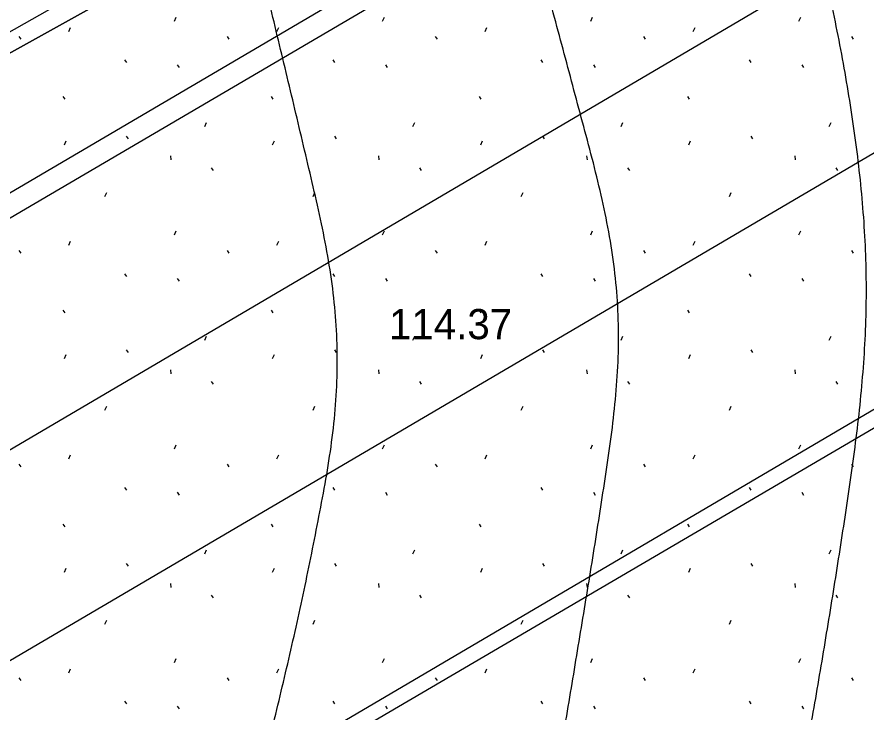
# Model space of a CAD drawing. Extents: x 412225 to 413380, y 4456471 to 4457189.
# Drawn here: x 413112.58 to 413146.44, y 4456831.09 to 4456858.79 of the extents above; entities that cross this region are included whole.
import ezdxf

# ---------------------------------------------------------------- set-up
doc = ezdxf.new("R2010")
doc.units = 0
for name, color, linetype in [('0_HALİHAZIR', 7, 'Continuous'), ('0_KADASTRO', 7, 'Continuous'), ('Level 41', 7, 'Continuous'), ('Level 54', 7, 'Continuous')]:
    doc.layers.add(name, color=color, linetype=linetype)

msp = doc.modelspace()

# ---------------------------------------------------------------- linework, layer by layer
at = {"layer": '0_HALİHAZIR'}
for points in [[(413308.103, 4456965.941), (413265.175, 4456940.384), (413047.239, 4456812.664), (412821.475, 4456681.363)], [(412841.576, 4456665.003), (413057.926, 4456790.466), (413273.464, 4456916.652), (413307.769, 4456936.91)], [(413101.589, 4456792.443), (413098.903, 4456797.22), (413080.986, 4456840.51), (413124.68, 4456865.219), (413175.605, 4456894.045), (413228.652, 4456922.382), (413248.055, 4456932.336), (413262.23, 4456891.913), (413262.792, 4456889.108), (413224.6, 4456867.435), (413186.768, 4456846.773), (413140.241, 4456816.307), (413141.746, 4456812.452)]]:
    msp.add_lwpolyline(points, dxfattribs=at)
for points in [[(413185.041, 4456825.516), (413184.865, 4456828.511), (413184.709, 4456831.506), (413184.582, 4456834.504), (413184.566, 4456837.501), (413184.755, 4456840.482), (413185.195, 4456843.441), (413185.816, 4456846.375), (413186.471, 4456849.302), (413187.02, 4456852.247), (413187.379, 4456855.217), (413187.478, 4456858.207), (413187.289, 4456861.187), (413186.83, 4456864.143), (413186.153, 4456867.062), (413185.337, 4456869.947), (413184.414, 4456872.8), (413183.4, 4456875.622), (413182.157, 4456878.336), (413180.573, 4456880.826), (413178.63, 4456883.087), (413176.485, 4456885.183), (413174.317, 4456887.257), (413172.212, 4456889.39), (413170.207, 4456891.616), (413168.296, 4456893.927), (413166.447, 4456896.289), (413164.633, 4456898.679), (413162.836, 4456901.081), (413161.013, 4456903.463), (413159.114, 4456905.781), (413157.112, 4456908.012), (413155.014, 4456910.154), (413152.817, 4456912.193), (413150.5, 4456914.086), (413148.049, 4456915.802), (413145.487, 4456917.358), (413142.861, 4456918.806), (413140.095, 4456919.757), (413137.24, 4456920.427), (413134.82, 4456921.48), (413134.285, 4456921.968)], [(413176.077, 4456827.781), (413176.22, 4456830.778), (413176.362, 4456833.775), (413176.504, 4456836.771), (413176.66, 4456839.767), (413176.833, 4456842.762), (413177.017, 4456845.756), (413177.167, 4456848.752), (413177.234, 4456851.75), (413177.176, 4456854.746), (413176.983, 4456857.738), (413176.658, 4456860.718), (413176.198, 4456863.68), (413175.553, 4456866.603), (413174.664, 4456869.456), (413173.469, 4456872.19), (413172, 4456874.791), (413170.353, 4456877.296), (413168.638, 4456879.757), (413166.915, 4456882.214), (413165.189, 4456884.667), (413163.46, 4456887.119), (413161.731, 4456889.57), (413160.001, 4456892.022), (413158.269, 4456894.471), (413156.53, 4456896.916), (413154.769, 4456899.344), (413152.97, 4456901.744), (413151.114, 4456904.1), (413149.196, 4456906.406), (413147.216, 4456908.659), (413145.17, 4456910.851), (413142.932, 4456912.817), (413140.47, 4456914.442), (413137.714, 4456915.514), (413134.845, 4456915.944), (413131.864, 4456916.014), (413129.101, 4456916.531), (413127.846, 4456917.947), (413127.82, 4456918.044)], [(413165.333, 4456820.404), (413165.763, 4456823.374), (413166.194, 4456826.342), (413166.626, 4456829.311), (413167.058, 4456832.28), (413167.457, 4456835.253), (413167.773, 4456838.234), (413167.922, 4456841.224), (413167.918, 4456844.221), (413167.789, 4456847.218), (413167.6, 4456850.211), (413167.353, 4456853.201), (413167.043, 4456856.184), (413166.668, 4456859.16), (413166.227, 4456862.127), (413165.713, 4456865.082), (413164.969, 4456867.974), (413163.873, 4456870.717), (413162.447, 4456873.344), (413160.86, 4456875.89), (413159.279, 4456878.439), (413157.699, 4456880.99), (413156.119, 4456883.54), (413154.538, 4456886.09), (413152.953, 4456888.637), (413151.333, 4456891.161), (413149.669, 4456893.656), (413147.947, 4456896.112), (413146.188, 4456898.542), (413144.392, 4456900.945), (413142.555, 4456903.316), (413140.673, 4456905.652), (413138.718, 4456907.925), (413136.505, 4456909.877), (413133.978, 4456911.273), (413131.134, 4456912.117), (413128.188, 4456912.678), (413125.238, 4456913.221), (413125.086, 4456913.253)], [(413152.977, 4456814.674), (413153.414, 4456817.641), (413153.905, 4456820.599), (413154.456, 4456823.548), (413155.022, 4456826.494), (413155.559, 4456829.446), (413156.035, 4456832.407), (413156.435, 4456835.379), (413156.76, 4456838.361), (413157.003, 4456841.35), (413157.144, 4456844.345), (413157.165, 4456847.343), (413157.059, 4456850.339), (413156.836, 4456853.329), (413156.505, 4456856.309), (413156.076, 4456859.277), (413155.559, 4456862.231), (413154.914, 4456865.158), (413154.049, 4456868.018), (413152.935, 4456870.789), (413151.62, 4456873.483), (413150.217, 4456876.134), (413148.775, 4456878.765), (413147.298, 4456881.376), (413145.787, 4456883.968), (413144.243, 4456886.54), (413142.653, 4456889.083), (413140.996, 4456891.582), (413139.263, 4456894.029), (413137.448, 4456896.417), (413135.549, 4456898.737), (413133.542, 4456900.962), (413131.409, 4456903.064), (413129.452, 4456904.831)], [(413141.718, 4456801.674), (413141.533, 4456804.668), (413141.345, 4456807.662), (413141.141, 4456810.655), (413141.173, 4456813.636), (413141.462, 4456816.58), (413142.039, 4456819.523), (413142.654, 4456822.459), (413143.242, 4456825.401), (413143.801, 4456828.349), (413144.332, 4456831.301), (413144.834, 4456834.259), (413145.31, 4456837.221), (413145.761, 4456840.187), (413146.143, 4456843.161), (413146.377, 4456846.145), (413146.398, 4456849.137), (413146.195, 4456852.125), (413145.812, 4456855.097), (413145.291, 4456858.05), (413144.659, 4456860.981), (413143.926, 4456863.889), (413143.086, 4456866.767), (413142.132, 4456869.609), (413141.061, 4456872.409), (413139.878, 4456875.164), (413138.596, 4456877.875), (413137.23, 4456880.545), (413135.801, 4456883.182), (413134.325, 4456885.794), (413132.81, 4456888.383), (413131.247, 4456890.943), (413129.626, 4456893.466), (413127.928, 4456895.938), (413126.108, 4456898.317), (413124.166, 4456900.595), (413123.465, 4456901.336)], [(413132.18, 4456801.915), (413131.534, 4456804.844), (413131.015, 4456807.794), (413130.788, 4456810.765), (413130.972, 4456813.727), (413131.528, 4456816.661), (413132.242, 4456819.574), (413132.925, 4456822.49), (413133.509, 4456825.432), (413134.034, 4456828.386), (413134.538, 4456831.343), (413135.031, 4456834.302), (413135.516, 4456837.263), (413135.979, 4456840.227), (413136.381, 4456843.199), (413136.542, 4456846.179), (413136.33, 4456849.135), (413135.763, 4456852.07), (413135.01, 4456854.974), (413134.234, 4456857.872), (413133.454, 4456860.768), (413132.672, 4456863.665), (413131.89, 4456866.561), (413131.111, 4456869.458), (413130.337, 4456872.356), (413129.44, 4456875.214), (413128.343, 4456877.967), (413127.02, 4456880.656), (413125.588, 4456883.292), (413124.135, 4456885.916), (413122.651, 4456888.523), (413121.13, 4456891.109), (413119.961, 4456893.047)], [(413121.034, 4456792.186), (413120.425, 4456795.121), (413119.728, 4456798.036), (413118.947, 4456800.933), (413118.191, 4456803.835), (413117.589, 4456806.767), (413117.389, 4456809.721), (413117.67, 4456812.66), (413118.378, 4456815.565), (413119.27, 4456818.429), (413120.188, 4456821.285), (413121.061, 4456824.154), (413121.868, 4456827.042), (413122.614, 4456829.948), (413123.318, 4456832.864), (413123.974, 4456835.791), (413124.571, 4456838.731), (413125.086, 4456841.685), (413125.333, 4456844.657), (413125.198, 4456847.612), (413124.705, 4456850.563), (413124.034, 4456853.487), (413123.342, 4456856.406), (413122.638, 4456859.322), (413121.932, 4456862.238), (413121.232, 4456865.155), (413120.548, 4456868.076), (413119.887, 4456871.002), (413119.247, 4456873.933), (413118.624, 4456876.868), (413118.012, 4456879.804), (413117.439, 4456882.749), (413116.97, 4456885.707), (413116.178, 4456888.543), (413115.645, 4456889.697)]]:
    msp.add_spline(points, degree=3, dxfattribs=at)
at = {"layer": '0_KADASTRO'}
msp.add_lwpolyline([(413081.18, 4456863.89), (413117.11, 4456885.191), (413114.748, 4456889.381), (413112.325, 4456893.68), (413114.95, 4456895.426), (413121.901, 4456899.897), (413122.52, 4456900.295), (413129.339, 4456904.681), (413130.089, 4456905.163), (413137.659, 4456910.032), (413145.228, 4456914.9), (413152.798, 4456919.769), (413160.405, 4456924.498), (413163.636, 4456926.04), (413168.332, 4456928.282), (413168.13, 4456928.684), (413171.177, 4456930.172), (413172.785, 4456930.957), (413174.23, 4456928.127), (413188.699, 4456899.781), (413084.666, 4456842.03), (413081.416, 4456862.441)], close=True, dxfattribs=at)
msp.add_lwpolyline([(413101.802, 4456789.154), (413081.926, 4456838.759), (413084.666, 4456842.03), (413188.699, 4456899.781), (413227.203, 4456920.401), (413243.637, 4456929.202), (413244.91, 4456926.572), (413267.668, 4456885.105), (413263.645, 4456882.832), (413242.448, 4456870.545), (413228.112, 4456862.238), (413213.766, 4456853.922), (413193.383, 4456842.116), (413184.691, 4456837.083), (413183.689, 4456836.502), (413165.406, 4456825.906)], dxfattribs=at)
at = {"layer": 'Level 41'}
for p, q in [((413118.851, 4456858.628), (413118.921, 4456858.788)), ((413127.144, 4456858.628), (413127.214, 4456858.788)), ((413135.437, 4456858.628), (413135.507, 4456858.788)), ((413143.73, 4456858.628), (413143.8, 4456858.788)), ((413114.641, 4456858.22), (413114.712, 4456858.38)), ((413122.934, 4456858.22), (413123.005, 4456858.38)), ((413131.227, 4456858.22), (413131.298, 4456858.38)), ((413139.52, 4456858.22), (413139.591, 4456858.38)), ((413112.653, 4456858.012), (413112.724, 4456857.906)), ((413120.946, 4456858.012), (413121.017, 4456857.906)), ((413129.239, 4456858.012), (413129.31, 4456857.906)), ((413137.532, 4456858.012), (413137.603, 4456857.906)), ((413145.825, 4456858.012), (413145.896, 4456857.906)), ((413116.861, 4456857.083), (413116.932, 4456856.976)), ((413125.154, 4456857.083), (413125.225, 4456856.976)), ((413133.447, 4456857.083), (413133.518, 4456856.976)), ((413141.74, 4456857.083), (413141.811, 4456856.976)), ((413118.96, 4456856.891), (413119.031, 4456856.784)), ((413127.253, 4456856.891), (413127.324, 4456856.784)), ((413135.546, 4456856.891), (413135.617, 4456856.784)), ((413143.839, 4456856.891), (413143.91, 4456856.784)), ((413114.405, 4456855.63), (413114.476, 4456855.523)), ((413122.698, 4456855.63), (413122.769, 4456855.523)), ((413130.991, 4456855.63), (413131.062, 4456855.523)), ((413139.284, 4456855.63), (413139.355, 4456855.523)), ((413120.057, 4456854.437), (413120.128, 4456854.596)), ((413128.35, 4456854.437), (413128.421, 4456854.596)), ((413136.643, 4456854.437), (413136.714, 4456854.596)), ((413144.936, 4456854.437), (413145.007, 4456854.596)), ((413114.463, 4456853.708), (413114.535, 4456853.868)), ((413116.928, 4456854.053), (413116.999, 4456853.946)), ((413122.756, 4456853.708), (413122.828, 4456853.868)), ((413125.221, 4456854.053), (413125.292, 4456853.946)), ((413131.049, 4456853.708), (413131.121, 4456853.868)), ((413133.514, 4456854.053), (413133.585, 4456853.946)), ((413139.342, 4456853.708), (413139.414, 4456853.868)), ((413141.807, 4456854.053), (413141.878, 4456853.946)), ((413118.686, 4456853.262), (413118.704, 4456853.102)), ((413126.979, 4456853.262), (413126.997, 4456853.102)), ((413135.272, 4456853.262), (413135.29, 4456853.102)), ((413143.565, 4456853.262), (413143.583, 4456853.102)), ((413120.316, 4456852.792), (413120.386, 4456852.685)), ((413128.609, 4456852.792), (413128.679, 4456852.685)), ((413136.902, 4456852.792), (413136.972, 4456852.685)), ((413145.195, 4456852.792), (413145.265, 4456852.685)), ((413116.079, 4456851.648), (413116.151, 4456851.808)), ((413124.372, 4456851.648), (413124.444, 4456851.808)), ((413132.665, 4456851.648), (413132.737, 4456851.808)), ((413140.958, 4456851.648), (413141.03, 4456851.808)), ((413118.851, 4456850.118), (413118.921, 4456850.278)), ((413127.144, 4456850.118), (413127.214, 4456850.278)), ((413135.437, 4456850.118), (413135.507, 4456850.278)), ((413143.73, 4456850.118), (413143.8, 4456850.278)), ((413114.641, 4456849.71), (413114.712, 4456849.87)), ((413122.934, 4456849.71), (413123.005, 4456849.87)), ((413131.227, 4456849.71), (413131.298, 4456849.87)), ((413139.52, 4456849.71), (413139.591, 4456849.87)), ((413112.653, 4456849.502), (413112.724, 4456849.396)), ((413120.946, 4456849.502), (413121.017, 4456849.396)), ((413129.239, 4456849.502), (413129.31, 4456849.396)), ((413137.532, 4456849.502), (413137.603, 4456849.396)), ((413145.825, 4456849.502), (413145.896, 4456849.396)), ((413116.861, 4456848.573), (413116.932, 4456848.466)), ((413125.154, 4456848.573), (413125.225, 4456848.466)), ((413133.447, 4456848.573), (413133.518, 4456848.466)), ((413141.74, 4456848.573), (413141.811, 4456848.466)), ((413118.96, 4456848.381), (413119.031, 4456848.274)), ((413127.253, 4456848.381), (413127.324, 4456848.274)), ((413135.546, 4456848.381), (413135.617, 4456848.274)), ((413143.839, 4456848.381), (413143.91, 4456848.274)), ((413114.405, 4456847.12), (413114.476, 4456847.013)), ((413122.698, 4456847.12), (413122.769, 4456847.013)), ((413130.991, 4456847.12), (413131.062, 4456847.013)), ((413139.284, 4456847.12), (413139.355, 4456847.013)), ((413120.057, 4456845.927), (413120.128, 4456846.086)), ((413128.35, 4456845.927), (413128.421, 4456846.086)), ((413136.643, 4456845.927), (413136.714, 4456846.086)), ((413144.936, 4456845.927), (413145.007, 4456846.086)), ((413116.928, 4456845.543), (413116.999, 4456845.436)), ((413125.221, 4456845.543), (413125.292, 4456845.436)), ((413133.514, 4456845.543), (413133.585, 4456845.436)), ((413141.807, 4456845.543), (413141.878, 4456845.436)), ((413114.463, 4456845.198), (413114.535, 4456845.358)), ((413122.756, 4456845.198), (413122.828, 4456845.358)), ((413131.049, 4456845.198), (413131.121, 4456845.358)), ((413139.342, 4456845.198), (413139.414, 4456845.358)), ((413118.686, 4456844.752), (413118.704, 4456844.592)), ((413126.979, 4456844.752), (413126.997, 4456844.592)), ((413135.272, 4456844.752), (413135.29, 4456844.592)), ((413143.565, 4456844.752), (413143.583, 4456844.592)), ((413120.316, 4456844.282), (413120.386, 4456844.175)), ((413128.609, 4456844.282), (413128.679, 4456844.175)), ((413136.902, 4456844.282), (413136.972, 4456844.175)), ((413145.195, 4456844.282), (413145.265, 4456844.175)), ((413116.079, 4456843.138), (413116.151, 4456843.298)), ((413124.372, 4456843.138), (413124.444, 4456843.298)), ((413132.665, 4456843.138), (413132.737, 4456843.298)), ((413140.958, 4456843.138), (413141.03, 4456843.298)), ((413118.851, 4456841.608), (413118.921, 4456841.768)), ((413127.144, 4456841.608), (413127.214, 4456841.768)), ((413135.437, 4456841.608), (413135.507, 4456841.768)), ((413143.73, 4456841.608), (413143.8, 4456841.768)), ((413114.641, 4456841.2), (413114.712, 4456841.36)), ((413122.934, 4456841.2), (413123.005, 4456841.36)), ((413131.227, 4456841.2), (413131.298, 4456841.36)), ((413139.52, 4456841.2), (413139.591, 4456841.36)), ((413112.653, 4456840.992), (413112.724, 4456840.886)), ((413120.946, 4456840.992), (413121.017, 4456840.886)), ((413129.239, 4456840.992), (413129.31, 4456840.886)), ((413137.532, 4456840.992), (413137.603, 4456840.886)), ((413145.825, 4456840.992), (413145.896, 4456840.886)), ((413116.861, 4456840.063), (413116.932, 4456839.956)), ((413125.154, 4456840.063), (413125.225, 4456839.956)), ((413133.447, 4456840.063), (413133.518, 4456839.956)), ((413141.74, 4456840.063), (413141.811, 4456839.956)), ((413118.96, 4456839.871), (413119.031, 4456839.764)), ((413127.253, 4456839.871), (413127.324, 4456839.764)), ((413135.546, 4456839.871), (413135.617, 4456839.764)), ((413143.839, 4456839.871), (413143.91, 4456839.764)), ((413114.405, 4456838.61), (413114.476, 4456838.503)), ((413122.698, 4456838.61), (413122.769, 4456838.503)), ((413130.991, 4456838.61), (413131.062, 4456838.503)), ((413139.284, 4456838.61), (413139.355, 4456838.503)), ((413120.057, 4456837.417), (413120.128, 4456837.576)), ((413128.35, 4456837.417), (413128.421, 4456837.576)), ((413136.643, 4456837.417), (413136.714, 4456837.576)), ((413144.936, 4456837.417), (413145.007, 4456837.576)), ((413116.928, 4456837.033), (413116.999, 4456836.926)), ((413125.221, 4456837.033), (413125.292, 4456836.926)), ((413133.514, 4456837.033), (413133.585, 4456836.926)), ((413141.807, 4456837.033), (413141.878, 4456836.926)), ((413114.463, 4456836.688), (413114.535, 4456836.848)), ((413122.756, 4456836.688), (413122.828, 4456836.848)), ((413131.049, 4456836.688), (413131.121, 4456836.848)), ((413139.342, 4456836.688), (413139.414, 4456836.848)), ((413118.686, 4456836.242), (413118.704, 4456836.082)), ((413126.979, 4456836.242), (413126.997, 4456836.082)), ((413135.272, 4456836.242), (413135.29, 4456836.082)), ((413143.565, 4456836.242), (413143.583, 4456836.082)), ((413120.316, 4456835.772), (413120.386, 4456835.665)), ((413128.609, 4456835.772), (413128.679, 4456835.665)), ((413136.902, 4456835.772), (413136.972, 4456835.665)), ((413145.195, 4456835.772), (413145.265, 4456835.665)), ((413116.079, 4456834.628), (413116.151, 4456834.788)), ((413124.372, 4456834.628), (413124.444, 4456834.788)), ((413132.665, 4456834.628), (413132.737, 4456834.788)), ((413140.958, 4456834.628), (413141.03, 4456834.788)), ((413118.851, 4456833.098), (413118.921, 4456833.258)), ((413127.144, 4456833.098), (413127.214, 4456833.258)), ((413135.437, 4456833.098), (413135.507, 4456833.258)), ((413143.73, 4456833.098), (413143.8, 4456833.258)), ((413114.641, 4456832.69), (413114.712, 4456832.85)), ((413122.934, 4456832.69), (413123.005, 4456832.85)), ((413131.227, 4456832.69), (413131.298, 4456832.85)), ((413139.52, 4456832.69), (413139.591, 4456832.85)), ((413112.653, 4456832.482), (413112.724, 4456832.376)), ((413120.946, 4456832.482), (413121.017, 4456832.376)), ((413129.239, 4456832.482), (413129.31, 4456832.376)), ((413137.532, 4456832.482), (413137.603, 4456832.376)), ((413145.825, 4456832.482), (413145.896, 4456832.376)), ((413116.861, 4456831.553), (413116.932, 4456831.446)), ((413125.154, 4456831.553), (413125.225, 4456831.446)), ((413133.447, 4456831.553), (413133.518, 4456831.446)), ((413141.74, 4456831.553), (413141.811, 4456831.446)), ((413118.96, 4456831.361), (413119.031, 4456831.254)), ((413127.253, 4456831.361), (413127.324, 4456831.254)), ((413135.546, 4456831.361), (413135.617, 4456831.254)), ((413143.839, 4456831.361), (413143.91, 4456831.254))]:
    msp.add_line(p, q, dxfattribs=at)
at = {"layer": 'Level 54'}
for points in [[(413046.364, 4456813.097), (413264.689, 4456941.261), (413308.102, 4456966.436)], [(413307.773, 4456937.825), (413273.289, 4456917.582), (413057.204, 4456790.554)], [(413211.499, 4456899.877), (413102.863, 4456836.014)], [(413108.887, 4456831.188), (413218.485, 4456895.526)]]:
    msp.add_lwpolyline(points, dxfattribs=at)

# ---------------------------------------------------------------- texts
at = {"layer": '0_HALİHAZIR'}
msp.add_text('114.37 ', height=1.2, dxfattribs=at).set_placement((413127.395, 4456845.967))

doc.saveas('drawing.dxf')
